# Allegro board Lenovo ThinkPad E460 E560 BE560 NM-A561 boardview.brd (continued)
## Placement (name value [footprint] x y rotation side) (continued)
NOREF#7  -  []  50.77 97.12 180 bottom
NOREF#8  -  []  28.57 60.15 90 bottom
NOREF#9  -  []  24.99 68.71 90 bottom
PC1  1U_0603_25V7K  [C_0603]  62.59 8.8 90 top
PC2  680P_0402_50V7-K  [C_0402]  238.87 174.28 0 bottom
PC3  0.1U_0402_6.3V  [C_0402]  238.89 175.17 0 bottom
PC4  1000P_0402_50V7-K  [C_0402]  233.51 158.66 270 bottom
PC5  100P_0402_50V8-J  [C_0402]  234.47 158.66 270 bottom
PC6  100P_0402_50V8J  [C_0402]  229.47 157.95 270 bottom
PC7  1000P_0402_50V7-K  [C_0402]  228.56 157.95 270 bottom
PC8  0.1U_0603_16V7K  [C_0603]  215.37 131.84 270 bottom
PC9  1000P_0402_50V  [C_0402]  192.49 181.14 180 bottom
PC10  0.01U_0402_25V  [C_0402]  202.11 183.63 270 bottom
PC101  470P_0402_50V  [C_0402]  223.25 162.68 180 bottom
PC102  0.022U_0402_25V  [C_0402]  223.7 159.81 270 bottom
PC103  10U_0805_25V6-K  [C_0805]  221.88 157.42 180 bottom
PC104  10U_0805_25V6-K  [C_0805]  224.85 175.81 180 bottom
PC105  0.1U_0402_25V7K  [C_0402]  180.45 165.04 270 bottom
PC106  0.1U_0402_25V7K  [C_0402]  181.31 165.04 0 bottom
PC107  1U_0603_25V7-K  [C_0603]  179.41 164.99 270 bottom
PC108  0.01U_0603_50V7K  [C_0603]  213.29 180 90 bottom
PC109  100P_0402_50V8-J  [C_0402]  180.98 165.9 0 bottom
PC110  2200P_0402_25V7-K  [C_0402]  193.66 172.15 270 bottom
PC111  47P_0402_50V8-J  [C_0402]  193.45 168.52 270 bottom
PC112  68P_0402_50V8-J  [C_0402]  192.49 168.52 270 bottom
PC113  10U_0805_25V6K  [C_0805]  192.31 170.93 90 bottom
PC114  10U_0805_25V6K  [C_0805]  190.58 170.93 90 bottom
PC115  1U_0603_25V  [C_0603]  182.3 169.1 270 bottom
PC116  4.7U_0603_10V6-M  [C_0603]  181.82 172.86 0 bottom
PC117  0.1U_0402_25V7K  [C_0402]  174.1 166.97 0 bottom
PC118  0.047U_0603_25V  [C_0603]  182.17 170.32 0 bottom
PC119  10U_0805_25V6-K  [C_0805]  204.02 184.02 270 bottom
PC120  10U_0805_25V6-K  [C_0805]  206.56 184.02 270 bottom
PC121  680P_0402_50V7K  [C_0402]  195.64 172.3 180 bottom
PC122  0.1U_0402_25V7K  [C_0402]  181.29 176.33 270 bottom
PC123  0.1U_0402_25V7K  [C_0402]  181.29 177.19 90 bottom
PC124  0.1U_0402_25V7K  [C_0402]  182.17 176.3 90 bottom
PC125  100P_0402_50V8J  [C_0402]  170.31 168.87 0 bottom
PC126  100P_0402_50V8J  [C_0402]  170.31 169.74 0 bottom
PC127  100P_0402_50V8J  [C_0402]  170.29 170.63 0 bottom
PC128  0.1U_0402_25V6  [C_0402]  175.24 177 180 bottom
PC201  0.1U_0402_25V6-K  [C_0402]  170.49 9.54 90 bottom
PC202  10U_0805_25V6-K  [C_0805]  172.7 9.01 90 bottom
PC203  0.1U_0603_25V7-M  [C_0603]  163.56 7.74 180 top
PC204  22U_0805_6.3V6-M  [C_0805]  153.93 9.03 90 bottom
PC205  22U_0805_6.3V6-M  [C_0805]  153.96 6.29 270 bottom
PC206  22U_0805_6.3V6-M  [C_0805]  152.13 6.29 270 bottom
PC207  22U_0805_6.3V6-M  [C_0805]  152.1 9.03 90 bottom
PC208  4.7U_0603_6.3V6-K  [C_0603]  169.54 4.64 0 bottom
PC209  680P_0402_50V7K  [C_0402]  165.56 9.97 180 top
PC210  2200P_0402_25V7-K  [C_0402]  150.7 9.49 90 bottom
PC211  0.1U_0402_25V6  [C_0402]  150.76 5.68 270 bottom
PC212  0.01U_0402_25V7-K  [C_0402]  166.86 4.18 270 bottom
PC213  0.1U_0402_25V6-K  [C_0402]  165.97 3.29 90 top
PC214  10U_0805_25V6-K  [C_0805]  179.61 6.28 270 bottom
PC215  0.1U_0402_25V6-K  [C_0402]  183.95 4.48 270 bottom
PC216  10U_0805_25V6-K  [C_0805]  181.34 6.28 270 bottom
PC217  0.1U_0603_25V7-M  [C_0603]  193.35 7.53 270 top
PC218  1U_0603_25V6M  [C_0603]  184.84 10.8 270 bottom
PC219  22U_0805_6.3V6-M  [C_0805]  200.46 6.29 270 bottom
PC220  22U_0805_6.3V6-M  [C_0805]  204.04 6.3 270 bottom
PC221  22U_0805_6.3V6-M  [C_0805]  202.24 6.29 270 bottom
PC222  22U_0805_6.3V6-M  [C_0805]  203.89 8.98 90 bottom
PC223  22U_0805_6.3V6-M  [C_0805]  200.31 8.98 90 bottom
PC224  22U_0805_6.3V6-M  [C_0805]  202.09 8.98 90 bottom
PC225  4.7U_0603_6.3V6-K  [C_0603]  183.55 9.4 90 bottom
PC226  680P_0402_50V7K  [C_0402]  190.94 3.09 0 top
PC227  2200P_0402_25V7-K  [C_0402]  205.49 5.7 270 bottom
PC228  0.1U_0402_25V6  [C_0402]  205.39 9.49 90 bottom
PC229  6800P_0402_25V7-K  [C_0402]  186.8 9.11 90 bottom
PC230  47P_0402_50V8-J  [C_0402]  171.38 9.54 90 bottom
PC231  47P_0402_50V8-J  [C_0402]  183.01 4.48 270 bottom
PC301  10U_0603_6.3V6M  [C_0603]  134.14 33.14 180 bottom
PC302  10U_0805_25V6-K  [C_0805]  140.54 27.6 270 bottom
PC303  10U_0805_25V6-K  [C_0805]  142.3 27.62 270 bottom
PC304  0.1U_0402_25V6  [C_0402]  136.1 29.81 90 bottom
PC305  47P_0402_50V8-J  [C_0402]  137.01 29.81 90 top
PC306  68P_0402_50V8J  [C_0402]  136.1 29.81 90 top
PC307  2200P_0402_25V  [C_0402]  137.01 29.81 90 bottom
PC308  10U_0603_6.3V6M  [C_0603]  132.49 35.63 270 bottom
PC309  0.1U_0402_6.3V7-K  [C_0402]  131.43 35.19 270 bottom
PC310  0.22U_0603_25V7K  [C_0603]  136.89 33.59 270 bottom
PC311  330U_D2_2V_R9M  [C_D2]  137.57 13.98 0 bottom
PC312  2200P_0402_25V7-K  [C_0402]  139.91 11.09 0 bottom
PC313  0.1U_0402_25V6  [C_0402]  132.34 12.26 180 bottom
PC314  470P_0402_50V7K  [C_0402]  131.55 41.06 0 bottom
PC315  0.033U_0402_16V7K  [C_0402]  132.34 39.38 180 bottom
PC316  1U_0402_10VA-K  [C_0402]  139.35 38.42 90 bottom
PC317  680P_0402_50V7K  [C_0402]  140.77 24.17 180 top
PC318  0.1U_0402_6.3V7-K  [C_0402]  134.25 41.82 180 bottom
PC319  0.1U_0402_16V  [C_0402]  135.08 41.82 0 bottom
PC401  0.01U_0402_25V7-K  [C_0402]  76.23 125.62 0 bottom
PC402  1U_0402_6.3V6-K  [C_0402]  76.23 124.75 0 bottom
PC403  0.1U_0402_6.3V6-K  [C_0402]  69.42 118.05 90 top
PC404  1000P_0402_25V7-K  [C_0402]  78.16 116.96 90 bottom
PC405  0.033U_0402_25V7K  [C_0402]  71.94 116.17 0 bottom
PC406  1000P_0402_25V7-K  [C_0402]  77.27 116.09 0 bottom
PC407  3300P_0402_50V7-K  [C_0402]  76.46 117.95 180 bottom
PC408  0.1U_0402_25V6-K  [C_0402]  76.59 120.56 90 bottom
PC409  15P_0402_50V8-J  [C_0402]  75.47 116.17 180 bottom
PC410  1500P_0402_50V7-K  [C_0402]  75.47 115.31 180 bottom
PC411  270P_0402_50V7-M  [C_0402]  71.15 118.99 270 top
PC412  1000P_0402_50V7-K  [C_0402]  73.11 118.96 270 top
PC413  1000P_0402_25V7-K  [C_0402]  63.89 125.03 0 bottom
PC414  0.1U_0402_25V6-K  [C_0402]  72.75 126.46 180 bottom
PC415  3300P_0402_50V7-K  [C_0402]  63.91 126.76 0 bottom
PC416  470P_0402_50V8-J  [C_0402]  68.84 123.64 90 top
PC417  0.1U_0402_16V7-K  [C_0402]  71.91 127.29 90 bottom
PC418  100P_0402_50V7-K  [C_0402]  70.08 126.46 0 bottom
PC419  1000P_0402_25V7-K  [C_0402]  70.08 127.34 0 bottom
PC420  2200P_0402_25V7-K  [C_0402]  68.36 128.23 270 bottom
PC421  470P_0402_50V8-J  [C_0402]  65.74 128.23 0 bottom
PC422  15P_0402_50V8-J  [C_0402]  67.47 126.48 0 bottom
PC423  1000P_0402_25V7-K  [C_0402]  62.9 122.77 90 bottom
PC424  0.1U_0402_25V6-K  [C_0402]  74.5 127.29 90 bottom
PC425  1000P_0402_25V7-K  [C_0402]  62.9 121.05 90 bottom
PC426  3300P_0402_50V7-K  [C_0402]  63.73 121.07 0 bottom
PC427  15P_0402_50V8-J  [C_0402]  63.73 119.34 0 bottom
PC428  0.01U_0402_25V6-K  [C_0402]  63.73 120.21 0 bottom
PC429  0.018U_0402_50V7-J  [C_0402]  63.96 117.39 90 bottom
PC430  270P_0402_50V7-M  [C_0402]  68.23 118.94 180 top
PC431  1000P_0402_50V7-K  [C_0402]  68.23 121.53 180 top
PC432  10U_0805_25V6-K  [C_0805]  138.46 97.14 270 bottom
PC433  10U_0805_25V6-K  [C_0805]  143.64 97.12 270 bottom
PC434  10U_0805_25V6-K  [C_0805]  141.92 97.12 270 bottom
PC435  10U_0805_25V6-K  [C_0805]  140.19 97.12 270 bottom
PC436  0.1U_0402_25V6  [C_0402]  137.06 96.1 270 bottom
PC437  2200P_0402_25V7-K  [C_0402]  135.29 96.1 270 bottom
PC438  47P_0402_50V8-J  [C_0402]  136.18 96.1 270 bottom
PC439  3300P_0402_50V7-K  [C_0402]  64.85 117.39 90 bottom
PC440  1000P_0402_50V7-K  [C_0402]  71.94 115.31 0 bottom
PC441  1U_0402_6.3V6-K  [C_0402]  66.71 116.12 270 bottom
PC442  0.22U_0603_25V7-K  [C_0603]  130.74 100.78 270 bottom
PC443  330U_D2_2VM_R9M  [C_D2]  124.99 109.82 90 bottom
PC444  1U_0402_10V  [C_0402]  125.51 103.65 0 bottom
PC445  680P_0402_50V7K  [C_0402]  143.97 113.48 0 bottom
PC446  10U_0805_25V6-K  [C_0805]  39.07 58.03 0 top
PC447  10U_0805_25V6-K  [C_0805]  39.07 58.03 0 bottom
PC448  10U_0805_25V6-K  [C_0805]  34.5 59.83 180 bottom
PC449  10U_0805_25V6-K  [C_0805]  34.5 59.83 180 top
PC450  0.1U_0402_25V6  [C_0402]  34.02 63.18 180 bottom
PC451  2200P_0402_25V7-K  [C_0402]  33.99 62.22 180 bottom
PC452  47P_0402_50V8-J  [C_0402]  33.99 61.28 180 bottom
PC453  0.22U_0603_25V7-K  [C_0603]  36.86 72.43 180 bottom
PC454  330U_D2_2VM_R9M  [C_D2]  45.29 80.38 180 bottom
PC455  1U_0402_10V  [C_0402]  39.83 76.47 270 bottom
PC456  680P_0402_50V7K  [C_0402]  48.6 59.53 90 top
PC457  10U_0805_25V6-K  [C_0805]  144.66 73.42 270 bottom
PC458  10U_0805_25V6-K  [C_0805]  142.93 73.45 270 bottom
PC459  0.1U_0402_25V6  [C_0402]  143.11 75.55 90 bottom
PC460  2200P_0402_25V7-K  [C_0402]  144 75.55 90 bottom
PC461  47P_0402_50V8-J  [C_0402]  144.89 75.55 90 bottom
PC462  0.22U_0603_25V7-K  [C_0603]  140.32 81.83 180 bottom
PC463  1U_0402_10V  [C_0402]  143.16 85.61 270 bottom
PC464  680P_0402_50V7K  [C_0402]  141.51 78.58 0 top
PC465  22U_0603_6.3V6M  [C_0603]  86.99 98.41 180 top
PC466  22U_0603_6.3V6M  [C_0603]  82.77 98.52 0 top
PC467  22U_0603_6.3V6M  [C_0603]  89.78 97.58 180 top
PC468  22U_0603_6.3V6M  [C_0603]  82.77 92.55 0 top
PC469  22U_0603_6.3V6M  [C_0603]  92.78 98.85 180 top
PC470  22U_0603_6.3V6M  [C_0603]  82.77 93.74 0 top
PC471  22U_0603_6.3V6M  [C_0603]  82.77 94.93 0 top
PC472  22U_0603_6.3V6M  [C_0603]  89.78 96.31 180 top
PC473  22U_0603_6.3V6M  [C_0603]  86.99 96.03 180 top
PC474  22U_0603_6.3V6M  [C_0603]  86.99 92.45 180 top
PC475  22U_0603_6.3V6M  [C_0603]  89.78 95.04 180 top
PC476  22U_0603_6.3V6M  [C_0603]  89.78 93.77 180 top
PC477  22U_0603_6.3V6M  [C_0603]  80.4 93.23 0 top
PC478  22U_0603_6.3V6M  [C_0603]  92.78 94.07 180 top
PC479  22U_0603_6.3V6M  [C_0603]  80.4 91.99 0 top
PC480  22U_0603_6.3V6M  [C_0603]  86.99 93.64 180 top
PC481  22U_0603_6.3V6M  [C_0603]  92.78 97.65 180 top
PC482  22U_0603_6.3V6M  [C_0603]  92.78 95.26 180 top
PC483  22U_0603_6.3V6M  [C_0603]  86.99 94.83 180 top
PC484  22U_0603_6.3V6M  [C_0603]  82.77 96.13 0 top
PC485  22U_0603_6.3V6M  [C_0603]  92.78 96.46 180 top
PC486  22U_0603_6.3V6M  [C_0603]  82.77 97.32 0 top
PC487  22U_0603_6.3V6M  [C_0603]  86.99 97.22 180 top
PC488  22U_0603_6.3V6M  [C_0603]  74.75 98.34 0 top
PC489  22U_0603_6.3V6M  [C_0603]  78.97 97.07 180 top
PC490  22U_0603_6.3V6M  [C_0603]  63.68 95.12 90 bottom
PC491  22U_0603_6.3V6M  [C_0603]  63.68 93.96 270 bottom
PC492  22U_0603_6.3V6M  [C_0603]  72.35 91.75 90 top
PC493  22U_0603_6.3V6M  [C_0603]  74.75 89.4 0 top
PC494  22U_0603_6.3V6M  [C_0603]  78.97 94.53 180 top
PC495  22U_0603_6.3V6M  [C_0603]  78.97 93.23 180 top
PC496  22U_0603_6.3V6M  [C_0603]  74.75 97.05 0 top
PC497  22U_0603_6.3V6M  [C_0603]  74.75 95.78 0 top
PC498  22U_0603_6.3V6M  [C_0603]  74.75 94.52 0 top
PC499  22U_0603_6.3V6M  [C_0603]  74.75 93.29 0 top
PC500  22U_0603_6.3V6M  [C_0603]  62.41 99.8 270 bottom
PC501  22U_0603_6.3V6M  [C_0603]  63.68 99.8 270 top
PC502  22U_0603_6.3V6M  [C_0603]  63.68 99.8 270 bottom
PC503  22U_0603_6.3V6M  [C_0603]  63.68 95.12 90 top
PC504  22U_0603_6.3V6M  [C_0603]  62.41 99.8 270 top
PC505  22U_0603_6.3V6M  [C_0603]  63.68 93.96 270 top
PC506  22U_0603_6.3V6M  [C_0603]  62.41 93.68 270 top
PC507  22U_0603_6.3V6M  [C_0603]  62.41 95.12 90 top
PC508  22U_0603_6.3V6M  [C_0603]  61.14 95.1 90 bottom
PC509  22U_0603_6.3V6M  [C_0603]  62.41 95.12 90 bottom
PC510  22U_0603_6.3V6M  [C_0603]  62.41 93.68 270 bottom
PC511  22U_0603_6.3V6M  [C_0603]  61.14 93.7 270 bottom
PC512  22U_0603_6.3V6M  [C_0603]  61.14 99.8 270 bottom
PC513  22U_0603_6.3V6M  [C_0603]  134.3 88.81 270 bottom
PC514  22U_0603_6.3V6M  [C_0603]  135.57 88.81 270 bottom
PC515  22U_0603_6.3V6M  [C_0603]  136.84 88.81 270 bottom
PC516  22U_0603_6.3V6M  [C_0603]  133.03 88.81 270 bottom
PC517  22U_0603_6.3V6M  [C_0603]  135.57 88.81 270 top
PC518  22U_0603_6.3V6M  [C_0603]  131.76 88.81 270 top
PC519  22U_0603_6.3V6M  [C_0603]  130.54 88.81 270 bottom
PC520  22U_0603_6.3V6M  [C_0603]  131.76 88.81 270 bottom
PC521  22U_0603_6.3V6M  [C_0603]  134.3 88.81 270 top
PC522  22U_0603_6.3V6M  [C_0603]  133.03 88.81 270 top
PC523  22U_0603_6.3V6M  [C_0603]  136.84 88.81 270 top
PC524  22U_0603_6.3V6M  [C_0603]  130.49 88.81 270 top
PC525  68U_25V_M_R0.36  [C_EEEFK1E680P]  32.54 52.39 180 bottom
PC526  68U_25V_M_R0.36  [C_EEEFK1E680P]  32.54 45.28 180 bottom
PC527  68U_25V_M_R0.36  [C_EEEFK1E680P]  38.87 51.47 270 bottom
PC528  33U_D2_25VM_R40M  [C_D2]  38.6 48.71 270 top
PC529  33U_D2_25VM_R40M  [C_D2]  43.55 48.71 270 top
PC601  0.1U_0402_25V6  [C_0402]  218.19 151.2 0 bottom
PC602  47P_0402_50V8-J  [C_0402]  196.4 142.43 180 top
PC603  2200P_0402_50V7K  [C_0402]  196.4 142.43 180 bottom
PC604  1U_0402_10V  [C_0402]  207.09 152.41 180 bottom
PC605  1U_0402_10V  [C_0402]  207.09 153.28 180 bottom
PC606  0.1U_0402_25V6  [C_0402]  196.4 141.54 180 bottom
PC607  10U_0805_25V6K  [C_0805]  196.22 143.88 180 top
PC608  0.22U_0603_25V  [C_0603]  213.99 145.77 0 top
PC609  100P_0402_50V8-J  [C_0402]  210.75 147.44 180 bottom
PC610  150P_0402_50V8-J  [C_0402]  208.06 146.57 0 bottom
PC611  10U_0805_25V6K  [C_0805]  196.22 143.88 180 bottom
PC612  0.22U_0603_25V  [C_0603]  206.69 149.11 90 bottom
PC613  330U_D2_2VM_R9M  [C_D2]  175.32 150.94 0 bottom
PC614  330U_D2_2VM_R9M  [C_D2]  175.32 146.24 0 bottom
PC615  0.1U_0402_25V6  [C_0402]  178.57 143.12 0 bottom
PC616  680P_0402_50V  [C_0402]  186.11 141.26 90 top
PC617  470P_0402_50V  [C_0402]  210.72 144.85 180 bottom
PC618  0.22U_0603_25V7-K  [C_0603]  206.81 156.78 270 bottom
PC619  330P_0402_50V7-K  [C_0402]  209 143.09 90 bottom
PC620  680P_0402_50V7-K  [C_0402]  208.08 144.01 270 bottom
PC621  330P_0402_50V7-K  [C_0402]  212.48 147.44 180 bottom
PC622  1000P_0402_25V7-K  [C_0402]  211.56 146.57 0 bottom
PC623  47P_0402_50V8-J  [C_0402]  196.37 154.09 180 top
PC624  2200P_0402_50V7K  [C_0402]  196.37 155.01 180 bottom
PC625  0.1U_0402_25V6  [C_0402]  196.37 154.09 180 bottom
PC626  10U_0805_25V6K  [C_0805]  196.25 152.77 180 bottom
PC627  10U_0805_25V6K  [C_0805]  196.25 152.77 180 top
PC628  0.22U_0603_25V  [C_0603]  213.99 146.98 0 top
PC629  330U_D2_2VM_R9M  [C_D2]  170.16 153.53 90 bottom
PC630  330U_D2_2VM_R9M  [C_D2]  170.52 142.74 180 bottom
PC631  0.1U_0402_25V6  [C_0402]  178.57 142.23 0 bottom
PC632  680P_0402_50V7K  [C_0402]  190.99 155.08 270 top
PC633  0.1U_0402_25V7K  [C_0402]  215.96 146.55 180 bottom
PC634  82N_0402_50V  [C_0402]  215.96 147.44 180 bottom
PC635  330P_0402_50V  [C_0402]  213.34 147.44 270 bottom
PC636  0.1U_0402_25V  [C_0402]  214.97 151.53 0 top
PC637  0.1U_0402_25V6  [C_0402]  214.31 143.91 90 bottom
PC701  0.1U_0402_16V7-K  [C_0402]  140.04 45.53 270 bottom
PC702  0.1U_0402_6.3V7-K  [C_0402]  141.81 44.64 180 bottom
PC703  0.01U_0402_25V7-K  [C_0402]  144.18 48.35 0 bottom
PC704  0.1U_0603_25V7K  [C_0603]  134.42 48.11 90 bottom
PC705  2.2U_0603_10V6-K  [C_0603]  144.89 51.53 270 bottom
PC706  68P_0402_50V8J  [C_0402]  142.45 53.41 180 top
PC707  10U_0805_25V6-K  [C_0805]  142.8 57.42 180 bottom
PC708  10U_0805_25V6-K  [C_0805]  142.8 55.67 180 bottom
PC709  2200P_0402_25V7-K  [C_0402]  142.45 54.29 180 bottom
PC710  0.1U_0402_25V6  [C_0402]  142.45 53.41 180 bottom
PC711  22U_0805_6.3V6-M  [C_0805]  133.28 63.64 180 bottom
PC712  22U_0805_6.3V6-M  [C_0805]  136.89 60.87 0 bottom
PC713  22U_0805_6.3V6-M  [C_0805]  136.89 62.57 0 bottom
PC714  47P_0402_50V8-J  [C_0402]  142.45 54.29 180 top
PC715  22U_0805_6.3V6-M  [C_0805]  133.28 61.46 180 bottom
PC716  2200P_0402_25V7-K  [C_0402]  132.37 67.6 180 bottom
PC717  0.1U_0402_25V6  [C_0402]  132.34 66.13 180 bottom
PC718  680P_0402_50V7K  [C_0402]  137.14 54.45 0 top
PC801  10U_0603_10V  [C_0603]  186.59 180.68 180 bottom
PC802  10U_0603_10V  [C_0603]  186.59 179.47 180 bottom
PC803  0.22U_0402_10V6-K  [C_0402]  184.16 185.4 180 bottom
PC804  680P_0402_50V  [C_0402]  182.81 183.68 90 top
PC805  22P_0402_50V  [C_0402]  190.18 184.01 270 bottom
PC806  22U_0805_6.3VAM  [C_0805]  171.91 181.6 180 bottom
PC807  22U_0805_6.3VAM  [C_0805]  171.91 179.87 180 bottom
PC808  0.1U_0402_25V6  [C_0402]  174.05 178.78 0 bottom
PD1  RB751V-40  [RB751V-40_SOD323-2]  71.23 14.16 0 top
PD2  1SS355  [RB751V-40_SOD323-2]  68.99 11.29 270 top
PD3  RB751V-40  [RB751V-40_SOD323-2]  71.23 12.51 0 top
PD4  -  [RB751V-40_SOD323-2]  244.46 162.09 180 top
PD5  -  [AZ5425-01F_DFN1006P2E2]  243.52 161.51 270 bottom
PD6  RB751V-40  [RB751V-40_SOD323-2]  230.87 153.46 180 top
PD7  -  [PESD5V0U2BT_SOT23-3]  200.21 182.03 0 top
PD101  RB751V-40  [RB751V-40_SOD323-2]  174.76 163.95 0 bottom
PD102  RB751V-40  [RB751V-40_SOD323-2]  187.25 166.73 180 bottom
PD103  RB751V-40  [RB751V-40_SOD323-2]  186.21 170.52 0 bottom
PD801  RB751V-40  [RB751V-40_SOD323-2]  181.54 186.2 0 top
PF1  7A_32V_0437007.WR  [F_0437007PWR]  236.3 159.4 90 bottom
PF2  12A_32V_0501012.WRS  [F_0437007PWR]  193.45 182.51 90 bottom
PJ201  -  [JUMP_43X79]  174.83 8.32 0 bottom
PJ202  -  [JUMP_43X118]  148.27 7.33 0 bottom
PJ203  -  [JUMP_43X79]  180.14 7.56 90 bottom
PJ204  -  [JUMP_43X118]  207.88 7.66 180 bottom
PJ301  -  [JUMP_43X118]  132.98 9.97 90 bottom
PJ302  -  [JUMP_43X118]  136.89 9.97 90 bottom
PJ303  -  [JUMP_43X39]  131.96 37.71 270 bottom
PJ304  -  [JUMP_43X79]  143.82 28.08 0 bottom
PJ701  -  [JUMP_43X79]  144.02 58.92 90 bottom
PJ702  -  [JUMP_43X118]  132.98 71.19 270 bottom
PJ703  -  [JUMP_43X118]  136.91 71.19 270 bottom
PJ801  -  [JUMP_43X39]  188.86 179.52 0 bottom
PJ802  -  [JUMP_43X39]  171.71 176.47 90 bottom
PL1  MURATA BLM18KG300TN1D  [TDK_MPZ1608S300AT_2P]  232.21 160.11 180 bottom
PL2  MURATA BLM18KG300TN1D  [TDK_MPZ1608S300AT_2P]  232.21 158.89 180 bottom
PL3  MURATA BLM18KG300TN1D  [TDK_MPZ1608S300AT_2P]  197.11 180.38 0 bottom
PL4  MURATA BLM18KG300TN1D  [TDK_MPZ1608S300AT_2P]  197.11 179.11 0 bottom
PL101  1UH_PCMB053T-1R0MS_20%  [CYNTE_PCMB053T-1R0MS_2P]  220.05 165.27 90 bottom
PL102  4.7UH_PCMB104T-4R7MS  [CYNTE_PCMB104T-100MS_2P]  201.56 171.97 0 bottom
PL201  2.2UH_PCMB063T-2R2MS_8A_20%  [CYNTE_PCMB063T-2R2MS_2P]  162.95 7.74 180 bottom
PL202  2.2UH_PCMB063T-2R2MS_8A_20%  [CYNTE_PCMB063T-2R2MS_2P]  191.4 7.71 0 bottom
PL301  1UH_PCMC063T-1R0MN_+-20%  [CYNTE_PCMB063T-1R0MS_2P]  134.58 18.28 90 bottom
PL401  BLM18KG300TN1D  [TDK_MPZ1608S300AT_2P]  143.54 100.37 0 bottom
PL402  BLM18KG300TN1D  [TDK_MPZ1608S300AT_2P]  143.54 99.15 0 bottom
PL403  CMLE064T-R15MS0R725-88(0.72mohm+/-5%)  [CYNTE_CMLE064T-R15MS0R66788_2P]  135.9 107.89 180 bottom
PL404  BLM18KG300TN1D  [TDK_MPZ1608S300AT_2P]  37.45 56.5 270 bottom
PL405  BLM18KG300TN1D  [TDK_MPZ1608S300AT_2P]  35.95 56.5 270 bottom
PL406  CMLE064T-R15MS0R725-88(0.72mohm+/-5%)  [CYNTE_CMLE064T-R15MS0R66788_2P]  46.13 69.15 90 bottom
PL407  BLM18KG300TN1D  [TDK_MPZ1608S300AT_2P]  145.98 74.08 0 top
PL408  0.47UH_PCMB063T-R47MS3R675_18A_20%(DCR+/-5%)  [CYNTE_CMLE064T-R15MS0R66788_2P]  134.6 77.84 90 bottom
PL601  MURATA BLM18KG300TN1D  [TDK_MPZ1608S300AT_2P]  200.49 143.4 0 bottom
PL602  MURATA BLM18KG300TN1D  [TDK_MPZ1608S300AT_2P]  200.51 144.74 0 bottom
PL603  .24UH 20% PCME063T-R24MS1R145 35A  [CYNTE_PCMB063T-1R0MS_2P]  182.02 138.17 180 bottom
PL604  .24UH 20% PCME063T-R24MS1R145 35A  [CYNTE_PCMB063T-1R0MS_2P]  181.49 157.11 180 bottom
PL701  1UH_PCMC063T-1R0MN_+-20%  [CYNTE_PCMB063T-1R0MS_2P]  134.52 52.08 90 bottom
PL801  1UH_PH041H-1R0MS_20%  [CYNTE_PH041H-1R0MS_2P]  180.5 182.31 180 bottom
PQ1  -  [MMBT3906_SOT23-3]  64.67 13.63 270 top
PQ2  -  [MMBT3904_SOT23-3]  66.66 9.59 90 top
PQ4  2N7002KDWH 2N SOT363-6  [2N7002BKS_SOT363-6]  240.7 158.97 270 bottom
PQ101  AON7466  [SIS406DN-T1-GE3_PAK1212-8-5]  225.35 159.7 90 bottom
PQ102  AON7466  [SIS406DN-T1-GE3_PAK1212-8-5]  221.9 161.28 270 bottom
PQ103  2N7002WT1G  [2N7002KW_SOT323-3]  223.4 159.15 270 top
PQ104  AON7466  [SIS406DN-T1-GE3_PAK1212-8-5]  214.81 178.75 90 bottom
PQ105  2N7002WT1G  [2N7002KW_SOT323-3]  173.16 163.97 270 bottom
PQ106  AON7408L  [SI7326DN-T1-E3_PAK1212-8]  197.82 170.83 270 bottom
PQ107  AON7408L  [SI7326DN-T1-E3_PAK1212-8]  194.95 173.8 90 bottom
PQ201  2N7002KDWH 2N  [2N7002BKS_SOT363-6]  173.74 5.53 270 bottom
PQ301  AON7408L  [SI7326DN-T1-E3_PAK1212-8]  134.85 26.74 180 bottom
PQ302  AON7534  [SI7326DN-T1-E3_PAK1212-8]  141.89 24.04 270 bottom
PQ401  TPCA8065-H  [TPCA8065-H_PPAK56-8-5]  132.92 102.81 0 bottom
PQ402  TPCA8057-H  [TPCA8059-H_PPAK56-8-5]  144.63 106.59 270 bottom
PQ403  TPCA8057-H  [TPCA8059-H_PPAK56-8-5]  144.63 112.05 270 bottom
PQ404  TPCA8065-H  [TPCA8065-H_PPAK56-8-5]  39.76 68.54 270 bottom
PQ405  TPCA8057-H  [TPCA8059-H_PPAK56-8-5]  51.21 59.81 180 bottom
PQ406  TPCA8057-H  [TPCA8059-H_PPAK56-8-5]  45.55 59.81 180 bottom
PQ407  AON7408L  [SI7326DN-T1-E3_PAK1212-8]  139.25 75.96 0 bottom
PQ408  AON7408L  [SI7326DN-T1-E3_PAK1212-8]  142.22 79.8 270 bottom
PQ601  TPCA8065-H  [TPCA8065-H_PPAK56-8-5]  194.8 136.01 90 bottom
PQ602  TPCA8057-H  [TPCA8059-H_PPAK56-8-5]  184.97 141.92 0 bottom
PQ603  TPCA8057-H  [TPCA8059-H_PPAK56-8-5]  192.59 141.92 180 top
PQ604  TPCA8065-H  [TPCA8065-H_PPAK56-8-5]  194.39 156.53 90 bottom
PQ605  TPCA8057-H  [TPCA8059-H_PPAK56-8-5]  192.41 153.46 180 bottom
PQ606  TPCA8057-H  [TPCA8059-H_PPAK56-8-5]  184.82 153.46 0 top
PR1  100K_0402_1%  [R_0402]  68.69 13.12 90 top
PR2  10K_0402_1%  [R_0402]  68.69 15.05 0 top
PR3  750K_0402_5%  [R_0402]  68.69 16.04 0 top
PR4  750_0402_1%  [R_0402]  238.77 161.46 90 bottom
PR5  1M_0402_5%  [R_0402]  243.67 158.54 180 bottom
PR6  0_0402_5%  [R_0402]  240.62 161.43 180 bottom
PR7  10K_0402_1%  [R_0402]  241.51 161.43 0 bottom
PR8  1M_0402_5%  [R_0402]  242.75 159.42 0 bottom
PR9  16.5K_0402_1%  [R_0402]  212.35 132.22 0 bottom
PR10  12.7K_0402_1%  [R_0402]  210.52 133.11 270 bottom
PR11  47K_0402_1%  [R_0402]  211.44 133.11 270 bottom
PR12  20K_0402_1%  [R_0402]  209.38 131.21 270 bottom
PR13  0_0402_5%  [R0402_SHORT]  215.22 128.49 90 bottom
PR14  100_0402_1%  [R_0402]  197.06 183.99 180 top
PR15  100_0402_1%  [R_0402]  197.06 184.85 180 top
PR16  100K_0402_1%  [R_0402]  203.46 185.08 0 top
PR17  10K_0402_1%  [R_0402]  204.37 184.16 180 top
PR18  3.01K_0402_1%  [R_0402]  227.7 154.68 270 top
PR19  43K_0402_1%  [R_0402]  228.59 155.63 270 top
PR101  0.01_1206_1%  [R_1206]  219.84 175.92 90 bottom
PR102  4.7_0603_5%  [R_0603]  224.24 161.91 180 top
PR103  499K_0402_1%  [R_0402]  212.17 180.91 270 bottom
PR104  1M_0402_5%  [R_0402]  226.32 158.51 90 top
PR105  1M_0402_5%  [R_0402]  226.02 157.16 180 top
PR106  10_0402_1%  [R_0402]  180.12 166.05 90 bottom
PR107  10_0402_1%  [R_0402]  179.23 166.05 90 bottom
PR108  1K_0402_1%  [R_0402]  180.98 166.77 0 bottom
PR109  0_0402_5%  [R0402_SHORT]  169.4 164.66 270 bottom
PR110  10K_0402_1%  [R_0402]  170.31 164.66 270 bottom
PR111  4.02K_0603_1%  [R_0603]  176.94 165.52 90 bottom
PR112  4.02K_0603_1%  [R_0603]  178.16 165.52 90 bottom
PR113  432K_0402_1%  [R_0402]  174.1 165.22 0 bottom
PR114  10_1206_5%  [R_1206]  183.62 168.62 0 bottom
PR115  68K_0402_1%  [R_0402]  174.1 166.11 0 bottom
PR116  2.2_0603_5%  [R_0603]  182.2 171.62 0 bottom
PR117  0.01_1206_1%  [R_1206]  209.8 178.98 180 bottom
PR118  0_0402_5%  [R0402_SHORT]  175.88 166.05 90 bottom
PR119  4.7_0603_5%  [R_0603]  196.55 172.3 0 bottom
PR120  0_0402_5%  [R0402_SHORT]  172.04 172.58 0 bottom
PR121  0_0402_5%  [R0402_SHORT]  172.04 173.47 0 bottom
PR122  0_0402_5%  [R0402_SHORT]  172.04 168.87 0 bottom
PR123  0_0402_5%  [R0402_SHORT]  172.04 169.74 0 bottom
PR124  0_0402_5%  [R0402_SHORT]  172.04 170.65 0 bottom
PR125  10_0603_5%  [R_0603]  180.33 176.13 180 bottom
PR126  0_0402_5%  [R0402_SHORT]  172.04 171.57 0 bottom
PR128  10_0603_5%  [R_0603]  180.33 177.33 180 bottom
PR129  0_0402_5%  [R0402_SHORT]  176.08 177.89 0 bottom
PR130  316K_0402_1%  [R_0402]  176.99 178.78 180 bottom
PR131  18.2K_0402_1%  [R_0402]  176.1 177.03 270 bottom
PR132  100K_0402_1%  [R_0402]  175.24 176.14 180 bottom
PR201  1M_0402_5%  [R_0402]  170.49 9.54 90 top
PR202  0_0603_5%  [R0603_SHORT]  165.92 7.74 180 top
PR203  0_0402_5%  [R0402_SHORT]  167.7 4.15 0 bottom
PR204  4.7_0603_5%  [R_0603]  163.63 9.97 180 top
PR205  0_0402_5%  [R0402_SHORT]  169.5 3.57 0 bottom
PR206  2.2K_0402_1%  [R_0402]  165.08 3.29 90 top
PR207  1K_0402_1%  [R_0402]  167.7 3.29 0 bottom
PR208  1M_0402_5%  [R_0402]  166.86 4.18 270 top
PR209  100K_0402_5%  [R_0402]  187.69 10.89 270 bottom
PR210  0_0402_5%  [R_0402]  188.55 10.89 270 bottom
PR211  0_0402_5%  [R_0402]  187.66 9.13 0 bottom
PR212  0_0603_5%  [R0603_SHORT]  191.98 6.06 90 top
PR213  0_0402_5%  [R0402_SHORT]  185.93 9.11 90 bottom
PR214  4.7_0603_5%  [R_0603]  191.78 4.23 0 top
PR215  1K_0402_1%  [R_0402]  186.82 10.86 180 bottom
PR216  47K_0402_1%  [R_0402]  174.71 2.99 90 bottom
PR217  47K_0402_1%  [R_0402]  173.82 2.99 90 bottom
PR301  100K_0402_1%  [R_0402]  140.24 40.3 180 bottom
PR302  220K_0402_1%  [R_0402]  140.24 37.56 180 bottom
PR303  2.2_0603_5%  [R_0603]  135.34 32.25 90 bottom
PR304  4.7_0603_5%  [R_0603]  138.61 24.42 90 top
PR305  7.87K_0402_1%  [R_0402]  131.55 41.92 0 bottom
PR306  5.1_0603_5%  [R_0603]  141.66 38.62 180 bottom
PR307  10K_0402_1%  [R_0402]  132.47 42.79 180 bottom
PR308  100K_0402_1%  [R_0402]  139.33 41.16 0 bottom
PR309  887K_0402_1%  [R_0402]  136.86 42.69 270 bottom
PR310  0_0402_5%  [R0402_SHORT]  133.33 42.66 90 bottom
PR311  0_0402_5%  [R_0402]  134.19 42.66 90 bottom
PR312  0_0402_5%  [R0402_SHORT]  136 43.55 180 bottom
PR313  47K_0402_5%  [R_0402]  136 42.69 180 bottom
PR401  1K_0402_5%  [R_0402]  77.15 126.48 180 bottom
PR402  2_0402_5%  [R_0402]  77.15 123.89 180 bottom
PR403  100_0402_5%  [R_0402]  70.16 116.73 270 top
PR404  47_0402_5%  [R_0402]  69.3 116.73 270 top
PR405  12K_0402_1%  [R_0402]  71.94 114.47 270 bottom
PR406  10K_0402_1%  [R_0402]  65.84 116.12 270 bottom
PR407  0_0402_5%  [R0402_SHORT]  67.6 115.23 90 bottom
PR408  0_0402_5%  [R0402_SHORT]  69.32 115.23 90 bottom
PR409  75_0402_5%  [R_0402]  71.05 116.14 270 bottom
PR410  51_0402_5%  [R_0402]  68.46 115.23 90 bottom
PR411  10_0402_5%  [R_0402]  70.19 115.23 90 bottom
PR412  7.5K_0603_1%  [R_0603]  70.8 113.7 270 bottom
PR413  16.5K_0402_1%  [R_0402]  68.23 122.8 180 top
PR414  3.24K_0402_1%  [R_0402]  78.19 118.71 180 bottom
PR415  3.24K_0402_1%  [R_0402]  77.3 116.96 90 bottom
PR416  910_0402_1%  [R_0402]  76.46 117.08 180 bottom
PR417  0_0402_5%  [R0402_SHORT]  76.56 119.72 0 bottom
PR418  61.9K_0402_1%  [R_0402]  77.45 121.48 270 bottom
PR419  2.49K_0402_1%  [R_0402]  76.31 116.19 270 bottom
PR420  48.7K_0402_1%  [R_0402]  72.24 118.96 270 top
PR421  107K_0402_1%  [R_0402]  70.29 118.07 90 top
PR422  2.05K_0402_1%  [R_0402]  73.64 126.43 90 bottom
PR423  10_0402_1%  [R_0402]  72.78 127.29 90 bottom
PR424  1.21K_0402_1%  [R_0402]  63.91 125.9 0 bottom
PR425  26.1K_0402_1%  [R_0402]  69.7 123.64 90 top
PR426  52.3K_0603_1%  [R_0603]  71 127.52 0 top
PR427  73.2K_0402_1%  [R_0402]  69.2 128.21 0 bottom
PR428  1K_0402_5%  [R_0402]  66.63 126.48 90 bottom
PR429  4.75K_0402_1%  [R_0402]  67.49 127.32 90 bottom
PR430  165K_0402_1%  [R_0402]  70.08 128.23 270 top
PR431  49.9_0402_1%  [R_0402]  65.77 126.48 90 bottom
PR432  12.4K_0402_1%  [R_0402]  69.22 126.46 90 bottom
PR433  2.7K_0402_1%  [R_0402]  63.73 123.66 0 bottom
PR434  2.7K_0402_1%  [R_0402]  63.73 122.8 0 bottom
PR435  0_0402_5%  [R0402_SHORT]  74.48 126.46 0 bottom
PR436  61.9K_0402_1%  [R_0402]  75.37 128.23 270 bottom
PR437  1K_0402_1%  [R_0402]  63.73 121.93 0 bottom
PR438  7.5K_0603_1%  [R_0603]  63.79 117.44 90 top
PR439  12K_0402_1%  [R_0402]  63.07 117.39 90 bottom
PR440  1.5K_0402_1%  [R_0402]  62.87 119.29 90 bottom
PR441  41.2K_0402_1%  [R_0402]  68.23 120.66 180 top
PR442  113K_0402_1%  [R_0402]  68.23 119.8 180 top
PR443  24K_0402_1%  [R_0402]  72.88 124.6 0 top
PR444  24K_0402_1%  [R_0402]  72.88 123.66 0 top
PR445  48.7K_0402_1%  [R_0402]  72.88 122.77 0 top
PR446  90.9K_0402_1%  [R_0402]  72.88 121.91 0 top
PR447  15.8K_0402_1%  [R_0402]  72.88 121.05 0 top
PR448  10K_0402_1%  [R_0402]  72.88 120.18 0 top
PR449  2.2_0603_1%  [R_0603]  129.32 99.35 180 bottom
PR450  4.7_0603_5%  [R_0603]  143.08 113.55 180 bottom
PR451  0_0402_5%  [R0402_SHORT]  71.94 111.22 90 bottom
PR452  0_0402_5%  [R0402_SHORT]  73.69 115.28 90 bottom
PR453  2.2_0603_1%  [R_0603]  35.41 73.7 90 bottom
PR454  4.7_0603_5%  [R_0603]  48.55 61.41 90 top
PR455  0_0402_5%  [R0402_SHORT]  73.64 129.66 270 bottom
PR456  0_0402_5%  [R0402_SHORT]  72.78 129.94 270 bottom
PR457  2.2_0603_1%  [R_0603]  138.97 83.25 90 bottom
PR458  4.7_0603_5%  [R_0603]  140.47 78.25 90 top
PR459  0_0402_5%  [R0402_SHORT]  62.72 117.39 90 top
PR460  0_0402_5%  [R0402_SHORT]  64.83 117.39 90 top
PR601  0_0603_5%  [R0603_SHORT]  204.81 152.19 180 bottom
PR602  0_0603_5%  [R0603_SHORT]  204.81 153.41 180 bottom
PR603  0_0402_5%  [R0402_SHORT]  221.37 151.2 180 bottom
PR604  10K_0402_1%  [R_0402]  208.97 146.57 180 top
PR605  0_0402_5%  [R0402_SHORT]  208.06 147.44 0 top
PR606  0_0402_5%  [R0402_SHORT]  219.11 150.05 180 bottom
PR607  4.7_0603_5%  [R_0603]  187.23 141.14 270 top
PR608  3.65K_0402_1%  [R_0402]  214.31 142.15 90 bottom
PR609  0_0402_5%  [R0402_SHORT]  219.11 155.54 180 bottom
PR610  0_0402_5%  [R0402_SHORT]  219.11 154.68 180 bottom
PR611  0_0402_5%  [R0402_SHORT]  219.11 152.08 180 bottom
PR612  0_0402_5%  [R0402_SHORT]  219.11 152.95 180 bottom
PR613  42.2K_0402_1%  [R_0402]  209 145.71 180 bottom
PR614  0_0603_5%  [R0603_SHORT]  209.15 149.19 180 bottom
PR615  0_0402_5%  [R0402_SHORT]  219.11 153.81 180 bottom
PR616  10K_0402_1%  [R_0402]  215.46 144.69 180 top
PR617  499_0402_1%  [R_0402]  209.84 145.68 90 bottom
PR618  1_0402_1%  [R_0402]  215.17 144.82 270 bottom
PR619  32.4K_0402_1%  [R_0402]  208.06 147.44 0 bottom
PR620  0_0603_5%  [R0603_SHORT]  209.33 156.66 180 bottom
PR621  0_0402_5%  [R0402_SHORT]  211.61 143.12 180 bottom
PR622  10_0402_1%  [R_0402]  209.86 143.09 90 bottom
PR623  1.1K_0402_1%  [R_0402]  210.7 145.68 90 bottom
PR624  2.7K_0402_1%  [R_0402]  209 144.85 180 bottom
PR625  0_0402_5%  [R0402_SHORT]  211.59 144.87 270 bottom
PR626  10_0402_1%  [R_0402]  211.56 145.71 0 bottom
PR627  10K_0402_5%  [R_0402]  213.59 154.7 90 top
PR628  10K_0402_1%  [R_0402]  211.87 155.61 270 top
PR629  10K_0402_1%  [R_0402]  212.73 155.61 270 top
PR630  4.7_0603_5%  [R_0603]  191.04 156.22 0 top
PR631  3.65K_0402_1%  [R_0402]  216.9 144.82 270 bottom
PR632  10K_0402_1%  [R_0402]  216.31 146.47 270 top
PR633  2.61K_0402_1%  [R_0402]  216.8 145.63 90 bottom
PR634  11K_0402_1%  [R_0402]  215.96 145.66 180 bottom
PR635  649_0402_1%  [R_0402]  214.2 147.44 270 bottom
PR636  1_0402_1%  [R_0402]  216.03 144.82 270 bottom
PR637  0_0402_5%  [R_0402]  214.46 154.7 90 top
PR638  100K_0402_1%  [R_0402]  215.32 155.61 270 top
PR639  100_0402_1%  [R_0402]  213.32 145.66 0 bottom
PR640  100K_0402_1%  [R_0402]  215.86 153.86 180 top
PR641  27.4K_0402_1%  [R_0402]  218.19 149.19 0 bottom
PR642  130K_0402  [R_0402]  215.88 152.39 180 top
PR643  10.7K_0402_1%  [R_0402]  220.53 150.28 0 bottom
PR701  0_0402_5%  [R0402_SHORT]  139.17 44.62 90 bottom
PR702  210K_0402_1%  [R_0402]  141.81 45.51 180 bottom
PR703  210K_0402_1%  [R_0402]  142.65 44.62 90 bottom
PR704  100K_0402_1%  [R_0402]  138.28 45.53 270 bottom
PR705  0_0402_5%  [R_0402]  137.34 46.55 270 bottom
PR706  0_0402_5%  [R_0402]  145.09 49.21 180 bottom
PR707  0_0603_5%  [R0603_SHORT]  136.2 49.38 270 bottom
PR708  4.7_0603_5%  [R_0603]  136.91 53.46 270 top
PR801  0_0402_5%  [R0402_SHORT]  182.2 187.47 0 top
PR802  1M_0402_5%  [R_0402]  183.24 186.29 0 bottom
PR803  4.7_0603_5%  [R_0603]  181.67 184.82 270 top
PR804  20K_0402_1%  [R_0402]  189.29 184.01 270 bottom
PR805  10K_0402_1%  [R_0402]  191.06 183.1 90 bottom
PRT1  540_0402NEW_30%  [R_0402]  32.98 66.38 90 bottom
PRT2  540_0402NEW_30%  [R_0402]  198.79 134.63 180 bottom
PRT3  540_0402NEW_30%  [R_0402]  131.55 29.45 270 bottom
PRT4  540_0402NEW_30%  [R_0402]  140.75 71.69 180 bottom
PRT5  540_0402NEW_30%  [R_0402]  133.43 96.03 180 bottom
PRT6  540_0402NEW_30%  [R_0402]  195.23 167.53 0 bottom
PRT7  100K_0402_1%_NCP15WF104F03RC  [R_0402]  97.31 96.69 90 top
PRT401  MURAT_NCP15WF104F03RC  [R_0402-TH]  132.01 112.31 0 bottom
PRT402  MURAT_NCP15WF104F03RC  [R_0402-TH]  128.38 103.67 180 bottom
PRT403  MURAT_NCP15WM224J03RC  [R_0402-TH]  41.79 74.97 270 bottom
PRT404  MURAT_NCP15WF104F03RC  [R_0402-TH]  35.44 69.99 180 bottom
PRT405  MURAT_NCP15WF104F03RC  [R_0402-TH]  130.36 82.97 90 bottom
PRT601  10K_0402_NTC  [R_0402]  177.55 134.02 180 bottom
PRT602  470K_0402NEW_3%  [R_0402]  201.76 137.83 270 bottom
PU1  -  [G718TM1U_SOT23-8]  213.77 130.93 270 bottom
PU101  BQ24780SRUYR  [BQ24780RUYR_QFN24_4X4]  178.49 169.71 180 bottom
PU201  -  [SYX198BQNC_QFN10_3X3]  166.63 6.57 90 bottom
PU202  -  [SYX198CQNC_QFN10_3X3]  187.84 7.61 270 bottom
PU301  RT8231AGQW  [RT8231AGQW_WQFN20_3X3]  134.14 37.23 0 bottom
PU401  -  [NCP81208MNTXG_QFN48_6X6]  68.36 124.17 270 bottom
PU402  -  [NCP81253MNTBG_DFN8_2X2]  126.35 101.13 90 bottom
PU403  NCP81151MNTBG_DFN8_2X2  [NCP81253MNTBG_DFN8_2X2]  37.22 75.71 0 bottom
PU404  -  [NCP81253MNTBG_DFN8_2X2]  140.65 85.54 0 bottom
PU601  -  [ISL62771HRTZ_TQFN40_5X5]  215.53 154.65 180 bottom
PU701  TPS51367RVER  [TPS51367RVER_QFN28_3P5X4P5]  139.12 48.1 90 bottom
PU801  RT8068AZQW  [RT8068AZQW_WDFN10_3X3]  183.22 182.18 90 bottom
Q1  S TR TTC4116FU NPN SC-70-3  [MMST3904-7-F_SOT323-3]  33.07 105.19 180 bottom
Q2  S TR TTC4116FU NPN SC-70-3  [MMST3904-7-F_SOT323-3]  50.78 38.64 180 bottom
Q5  2N7002WT1G_1N_SC-70-3  [2N7002KW_SOT323-3]  214.15 33.92 180 top
Q6  -  [2N7002KDWH_SOT363-6]  206.94 137.45 0 top
Q22  -  [AO3401A_SOT23-3]  13.39 101.03 0 bottom
Q23  -  [AO4430L_SO8]  66.94 59.22 270 top
Q24  -  [2N7002KDWH_SOT363-6]  132.96 45.85 180 bottom
Q26  -  [AO3413_SOT23-3]  217.53 36.29 180 top
Q27  -  [AO3413_SOT23-3]  120.91 126.48 270 bottom
QC1  -  [2N7002KDWH_SOT363-6]  77.26 131.65 270 bottom
QC2  -  [2N7002KDWH_SOT363-6]  115.55 95.98 90 bottom
QC3  -  [2N7002KDWH_SOT363-6]  75.96 132.45 270 top
QD1  -  [DTC115TMT2L_VMT3]  109.4 21.76 270 top
QE1  2N7002WT1G_1N_SC-70-3  [2N7002KW_SOT323-3]  185.98 38.1 0 top
QG1  -  [AO3413_SOT23-3]  199.8 67.5 90 top
QG2  -  [2N7002KDWH_SOT363-6]  211.5 67.06 0 top
QL2  -  [AO3413_SOT23-3]  51.72 125.01 270 top
QL3  2N7002WT1G_1N_SC-70-3  [2N7002KW_SOT323-3]  55.06 121.58 270 top
QT1  -  [2N7002KDWH_SOT363-6]  16.06 90.21 270 bottom
QV1  2N7002WT1G_1N_SC-70-3  [2N7002KW_SOT323-3]  155.4 114.47 90 top
QV4  S TR TTC4116FU NPN SC-70-3  [MMST3904-7-F_SOT323-3]  171.92 130.98 90 top
QV5  -  [2N7002KDWH_SOT363-6]  162.47 143.89 0 top
QV6  -  [AO3413_SOT23-3]  174.58 129.28 0 top
QV9  -  [AO4430L_SO8]  183.78 128.44 90 bottom
QV17  2N7002WT1G_1N_SC-70-3  [2N7002KW_SOT323-3]  190.3 130 180 top
QV18  -  [2N7002KDWH_SOT363-6]  186.6 128.78 0 top
QV19  -  [2N7002KDWH_SOT363-6]  178.68 125.61 270 top
QV23  -  [2N7002KDWH_SOT363-6]  165.55 180.49 90 top
QV24  TPCA8057-H  [TPCA8059-H_PPAK56-8-5]  167.03 186.15 270 top
R2  100K_0402_5%  [R_0402]  92.11 139.41 135 bottom
R3  10K_0402_5%  [R_0402]  114.76 185.13 180 bottom
R17  0_0402_5%  [R_0402]  92.58 141.37 45 bottom
R18  100K_0402_5%  [R_0402]  88.95 132.37 135 bottom
R21  100K_0402_5%  [R_0402]  100.2 132.94 135 top
R25  2.2K_0402_1%  [R_0402]  98.93 131.67 135 top
R26  100K_0402_5%  [R_0402]  98.13 131 135 top
R28  47K_0402_5%  [R_0402]  213.87 36.26 270 top
R51  10K_0402_5%  [R_0402]  214.79 35.35 90 top
R59  4.7K_0402_5%  [R_0402]  182.94 123.94 270 top
R60  4.7K_0402_5%  [R_0402]  182.07 123.94 270 top
R61  4.7K_0402_5%  [R_0402]  30.88 104.03 0 top
R63  4.7K_0402_5%  [R_0402]  30.88 97.14 0 top
R64  0_0402_5%  [R0402_SHORT]  30.96 102.25 90 top
R65  4.7K_0402_5%  [R_0402]  30.88 96.25 0 top
R66  0_0402_5%  [R_0402]  31.85 102.25 90 top
R67  100K_0402_5%  [R_0402]  30.88 99.45 0 top
R68  0_0603_5%  [R0603_SHORT]  60.03 120.84 90 bottom
R69  100K_0402_5%  [R_0402]  211.31 32.53 180 top
R70  0_0402_5%  [R0402_SHORT]  214.99 92.75 0 top
R71  100K_0402_5%  [R_0402]  219.92 122.29 0 bottom
R89  100_0402_1%  [R_0402]  240.09 166.16 180 bottom
R90  100_0402_1%  [R_0402]  240.09 167.04 180 bottom
R91  100K_0402_5%  [R_0402]  240.09 165.27 180 bottom
R105  0_0402_5%  [R_0402]  32.62 104.92 180 top
R106  100K_0402_5%  [R_0402]  232.16 146.97 225 bottom
R107  100K_0402_5%  [R_0402]  230.24 145.06 45 bottom
R108  100K_0402_5%  [R_0402]  22.66 54.65 0 top
R111  300_0402_5%  [R_0402]  172.4 120.61 270 top
R112  1K_0603_5%  [R_0603]  231.98 156.45 270 bottom
R150  0_0402_5%  [R_0402]  223.75 60.36 0 bottom
R151  0_0402_5%  [R_0402]  240.04 171.87 180 bottom
R152  0_0402_5%  [R_0402]  240.04 172.76 180 bottom
R153  100K_0402_5%  [R_0402]  220.45 45.12 0 bottom
R154  0_0805_5%  [R_0805]  224.34 49.35 270 bottom
R156  100K_0402_5%  [R_0402]  205.92 141.39 270 top
R157  100K_0402_5%  [R_0402]  206.94 141.39 270 top
R159  47_0603_5%  [R_0603]  209.51 138.77 270 top
R163  0_0402_5%  [R_0402]  239.75 175.06 90 top
R164  0_0402_5%  [R_0402]  238.79 175.06 90 top
R165  0_0402_5%  [R_0402]  89.96 123.05 45 top
R166  0_0402_5%  [R_0402]  89.29 123.71 45 top
R167  0_0402_5%  [R_0402]  88.52 124.24 45 top
R168  0_0402_5%  [R_0402]  87.88 124.89 45 top
R169  0_0402_5%  [R_0402]  232.34 143.17 90 top
R170  0_0402_5%  [R_0402]  231.45 143.17 90 top
R171  0_0402_5%  [R_0402]  238.52 155.43 225 bottom
R172  0_0402_5%  [R_0402]  239.23 154.71 225 bottom
R173  0_0402_5%  [R_0402]  233.74 159.68 0 top
R174  0_0402_5%  [R_0402]  233.74 158.66 0 top
R175  0_0402_5%  [R_0402]  228.53 143.68 90 top
R176  0_0402_5%  [R_0402]  229.55 143.68 90 top
R177  0_0402_5%  [R_0402]  239.4 179.62 0 top
R178  0_0402_5%  [R_0402]  239.4 180.63 0 top
R217  100K_0402_5%  [R_0402]  234.98 145.25 0 top
R224  2.2K_0402_5%  [R_0402]  15.55 67.4 90 bottom
R225  2.2K_0402_5%  [R_0402]  14.66 67.4 90 bottom
R229  0_0402_5%  [R0402_SHORT]  17.33 80.25 270 top
R230  0_0402_5%  [R0402_SHORT]  17.33 82.54 270 top
R231  0_0402_5%  [R0402_SHORT]  17.33 84.83 270 top
R233  100K_0402_5%  [R_0402]  227.59 130.34 180 bottom
R234  100K_0402_5%  [R_0402]  227.59 129.45 180 bottom
R235  0_0402_5%  [R_0402]  227.59 131.23 180 bottom
R236  0_0805_5%  [R_0805]  247.33 159.68 90 bottom
R237  0_0805_5%  [R_0805]  245.55 159.68 90 bottom
R238  1K_0402_5%  [R_0402]  221.16 15.86 270 top
R239  1K_0402_5%  [R_0402]  239.12 170.98 0 bottom
R484  20K_0402_1%  [R_0402]  34.68 15.38 270 top
R9449  100K_0402_5%  [R_0402]  112.83 72.05 270 top
R9460  0_0402_5%  [R0402_SHORT]  212.22 31.54 90 top
R9472  0_0402_5%  [R_0402]  236.48 141.77 0 top
R9473  0_0402_5%  [R_0402]  236.48 140.88 0 top
R9474  0_0805_5%  [R0805_SHORT]  102.81 134.68 135 top
R9475  0_0402_5%  [R0402_SHORT]  99.57 132.3 135 top
R9476  20K_0402_1%  [R_0402]  35.57 15.38 270 top
R9477  10K_0402_5%  [R_0402]  118.57 116.04 270 bottom
R9478  0_0402_5%  [R_0402]  120.38 68.11 0 top
R9479  33_0402_5%  [R_0402]  115.91 115.12 90 bottom
R9480  10K_0402_5%  [R_0402]  112.91 125.26 270 bottom
R9481  33_0402_5%  [R_0402]  113.24 115.12 90 bottom
R9482  33_0402_5%  [R_0402]  116.8 115.12 90 bottom
R9483  33_0402_5%  [R_0402]  117.68 115.12 90 bottom
R9484  10K_0402_5%  [R_0402]  110.98 118.78 0 bottom
R9485  10K_0402_5%  [R_0402]  71.33 53.96 270 top
R9486  100K_0402_5%  [R_0402]  135.06 46.62 180 bottom
R9487  0_0402_5%  [R_0402]  70.41 53.05 90 top
R9488  10K_0402_1%  [R_0402]  129.34 67.98 90 top
R9489  10K_0402_5%  [R_0402]  122.66 125.8 90 bottom
R9490  0_0805_5%  [R_0805]  65.88 112.05 0 top
R9491  100_0402_5%  [R_0402]  117.07 126.43 180 bottom
R9492  0_0402_5%  [R_0402]  126.24 66.52 180 top
R9493  10K_0402_5%  [R_0402]  126.24 67.41 180 top
RA1  0_0805_5%  [R0805_SHORT]  194.1 20.44 0 top
RA2  0_0805_5%  [R_0805]  207.19 14.76 270 top
RA3  0_0805_5%  [R_0805]  205.47 13.06 90 top
RA4  0_0805_5%  [R0805_SHORT]  200.42 14.52 180 top
RA5  33_0402_5%  [R_0402]  209.86 26.99 270 top
RA8  BLM18PG221SN1D_2P  [MURAT_BLM18PG221SN1D_2P]  201.49 22.39 180 top
RA9  BLM18PG221SN1D_2P  [MURAT_BLM18PG221SN1D_2P]  201.49 24.68 180 top
RA10  BLM18PG221SN1D_2P  [MURAT_BLM18PG221SN1D_2P]  201.49 21.12 180 top
RA11  33_0402_5%  [R_0402]  200.21 29.1 0 top
RA12  BLM18PG221SN1D_2P  [MURAT_BLM18PG221SN1D_2P]  201.49 18.84 180 top
RA13  10K_0402_5%  [R_0402]  202.85 28.21 270 top
RA14  100_0402_5%  [R_0402]  213.85 17.54 0 top
RA15  100_0402_5%  [R_0402]  213.85 18.43 0 top
RA16  3K_0402_5%  [R_0402]  216.64 12.16 90 top
RA17  75_0402_5%  [R_0402]  216.64 11.34 270 top
RA18  5.11K_0402_1%  [R_0402]  215.12 22.29 180 top
RA19  100_0402_5%  [R_0402]  213.85 19.32 0 top
RA20  20K_0402_1%  [R_0402]  215.12 24.07 180 top
RA21  39.2K_0402_1%  [R_0402]  215.12 23.18 180 top
RA22  3K_0402_5%  [R_0402]  218.6 12.16 90 top
RA23  75_0402_5%  [R_0402]  218.6 11.34 270 top
RA24  100_0402_5%  [R_0402]  213.85 20.21 0 top
RA25  0_0402_5%  [R_0402]  196.04 26.38 270 top
RA27  0_0402_5%  [R0402_SHORT]  196.93 26.38 270 top
RA28  0_0402_5%  [R0402_SHORT]  214.97 27.6 270 top
RA29  47K_0402_5%  [R_0402]  217.94 22.32 180 top
RA30  0_0805_5%  [R0805_SHORT]  204.01 14.47 180 top
RA31  33_0402_5%  [R_0402]  215.12 24.96 180 top
RA32  0_0805_5%  [R0805_SHORT]  214.81 14.23 270 top
RC1  2.2K_0402_5%  [R_0402]  116.39 99.86 180 top
RC2  2.2K_0402_5%  [R_0402]  118.24 98.82 180 top
RC3  51_0201_5%  [R_0201]  73.97 115.44 90 top
RC4  51_0201_5%  [R_0201]  73.84 110.81 90 top
RC5  499_0402_1%  [R_0402]  71.67 113.64 0 top
RC6  51_0201_5%  [R_0201]  75.85 114.02 180 bottom
RC8  121_0402_1%  [R_0402]  98.61 82.22 270 top
RC9  80.6_0402_1%  [R_0402]  100.89 82.22 270 top
RC10  100_0402_1%  [R_0402]  100.01 82.22 270 top
RC11  0_0402_5%  [R0402_SHORT]  119.06 74.46 180 top
RC12  20K_0402_5%  [R_0402]  117.15 74.59 270 top
RC13  10M_0402_5%  [R_0402]  115.42 88.91 270 top
RC14  20K_0402_5%  [R_0402]  116.26 74.59 270 top
RC16  1M_0402_5%  [R_0402]  115.37 74.59 270 top
RC19  220_0402_1%  [R_0402]  70.01 109.21 90 top
RC20  56_0402_1%  [R_0402]  70.57 111.62 90 top
RC21  0_0402_5%  [R0402_SHORT]  99.04 71.16 0 top
RC24  22_0402_5%  [R_0402]  108.64 69.59 270 top
RC26  100K_0402_5%  [R_0402]  50.98 108.07 0 top
RC27  10K_0402_5%  [R_0402]  105.07 72.18 0 top
RC29  10K_0402_5%  [R_0402]  86.23 119.5 270 bottom
RC30  1M_0402_5%  [R_0402]  90.56 117.32 180 bottom
RC31  51_0201_5%  [R_0201]  76.35 115.99 0 top
RC32  10K_0402_5%  [R_0402]  85.6 117.13 180 bottom
RC34  51_0201_5%  [R_0201]  76.35 116.63 0 top
RC40  0_0402_5%  [R0402_SHORT]  112.13 110.99 270 bottom
RC41  0_0402_5%  [R0402_SHORT]  104.21 70.27 180 top
RC47  0_0402_5%  [R_0402]  106.86 69.59 270 top
RC48  33_0402_5%  [R_0402]  47.73 108.14 180 top
RC52  8.2K_0402_5%  [R_0402]  109.53 69.59 270 top
RC53  1K_0402_1%  [R_0402]  71.23 110.25 270 bottom
RC54  0_0402_5%  [R_0402]  70.34 110.25 270 bottom
RC55  49.9_0402_1%  [R_0402]  111.89 72.05 180 top
RC56  49.9_0402_1%  [R_0402]  53.02 102.02 270 top
RC67  10K_0402_5%  [R_0402]  119.87 94.5 90 bottom
RC70  10K_0402_5%  [R_0402]  120.76 94.25 90 bottom
RC71  10K_0402_5%  [R_0402]  118.95 95.42 270 bottom
RC74  10K_0402_5%  [R_0402]  120.96 91.91 90 bottom
RC83  1K_0402_5%  [R_0402]  116.19 94.81 180 bottom
RC86  10K_0402_5%  [R_0402]  114.13 98.69 90 bottom
RC88  10K_0402_5%  [R_0402]  113.24 98.69 90 bottom
RC92  499_0402_1%  [R_0402]  115.42 97.32 0 top
RC93  499_0402_1%  [R_0402]  115.27 93.82 0 bottom
RC95  8.2K_0402_5%  [R_0402]  120.63 75.83 0 top
RC97  20K_0402_5%  [R_0402]  120.17 72.07 180 top
RC98  1K_0402_5%  [R_0402]  120.17 71.16 180 top
RC99  1K_0402_5%  [R_0402]  121.16 71.41 90 top
RC100  20K_0402_5%  [R_0402]  121.16 73.14 90 top
RC101  1K_0402_5%  [R_0402]  123.88 72.23 90 top
RC102  33_0402_5%  [R_0402]  172.01 55.53 90 top
RC103  33_0402_5%  [R_0402]  138.16 122.49 0 bottom
RC104  1K_0402_5%  [R_0402]  67.82 109.82 90 top
RC105  1K_0402_5%  [R_0402]  67.75 110.53 180 bottom
RC106  4.7K_0402_5%  [R_0402]  79.3 129.88 90 bottom
RC107  4.7K_0402_5%  [R_0402]  76.54 129.22 180 bottom
RC108  10K_0402_5%  [R_0402]  173.46 133.14 0 top
RC109  0_0402_5%  [R0402_SHORT]  114.08 72.58 270 top
RC117  1K_0402_5%  [R_0402]  119.97 111.29 270 bottom
RC118  1K_0402_5%  [R_0402]  120.38 117.2 0 bottom
RC120  100_0402_1%  [R_0402]  96.25 117.64 0 top
RC121  0_0402_5%  [R0402_SHORT]  97.53 115.09 90 top
RC123  10K_0402_5%  [R_0402]  68.26 112.26 0 bottom
RC124  0_0402_5%  [R0402_SHORT]  60.2 110.99 270 top
RC125  100_0402_1%  [R_0402]  61.17 112 180 top
RC126  0_0402_5%  [R0402_SHORT]  100.72 115.25 90 top
RC127  0_0402_5%  [R_0402]  115.37 75.48 90 top
RC132  0_0402_5%  [R0402_SHORT]  116.26 75.48 90 top
RC142  0_0402_5%  [R0402_SHORT]  98.42 115.09 90 top
RC143  100_0402_1%  [R_0402]  98.04 117.63 90 top
RC144  1K_0402_1%  [R_0402]  66.02 110.15 0 top
RC151  49.9_0402_1%  [R_0402]  111.89 71.16 180 top
RC152  49.9_0402_1%  [R_0402]  73.08 110.58 90 top
RC159  100K_0402_5%  [R_0402]  119.44 99.1 270 top
RC165  10K_0402_5%  [R_0402]  124.44 78.09 270 top
RC166  10K_0402_5%  [R_0402]  123.5 78.09 270 top
RC173  0_0603_5%  [R0603_SHORT]  126.82 87.72 180 top
RC176  0_0805_5%  [R0805_SHORT]  139.56 87.81 90 top
RC183  0_0402_5%  [R0402_SHORT]  59.32 110.99 270 top
RC184  100_0402_1%  [R_0402]  59.34 112 180 top
RC185  0_0402_5%  [R0402_SHORT]  99.8 115.25 90 top
RC189  100_0402_1%  [R_0402]  96.96 82.51 90 top
RC192  100_0402_1%  [R_0402]  95.38 89.02 180 top
RC197  0_0603_5%  [R0603_SHORT]  97.59 106.53 180 top
RC200  49.9_0402_1%  [R_0402]  54.11 101.08 90 top
RC201  1K_0402_1%  [R_0402]  66.83 111.39 0 bottom
RC204  100K_0402_5%  [R_0402]  121.24 99.99 180 top
RC209  100K_0402_5%  [R_0402]  121.23 98.85 180 top
RC277  2.2K_0402_5%  [R_0402]  52.91 104.33 0 top
RC286  0_0402_5%  [R_0402]  104.21 71.29 180 top
RC287  2.2K_0402_5%  [R_0402]  52.91 103.44 0 top
RC288  100K_0402_5%  [R_0402]  117.99 99.99 0 top
RC293  0_0603_5%  [R0603_SHORT]  95.81 83.03 90 top
RC294  1K_0402_5%  [R_0402]  71.95 115.36 180 top
RC295  0_0402_5%  [R0402_SHORT]  59.24 75.48 90 top
RC296  0_0402_5%  [R0402_SHORT]  107.83 83 180 top
RC297  1K_0402_5%  [R_0402]  103.23 68.49 0 top
RC298  8.2K_0402_5%  [R_0402]  113.48 113.26 180 bottom
RC299  1K_0402_5%  [R_0402]  99.96 72.05 180 top
RC300  20K_0402_5%  [R_0402]  121.52 74.92 180 top
RC301  20K_0402_5%  [R_0402]  103.23 67.6 0 top
RC302  20K_0402_5%  [R_0402]  99.24 70.17 270 top
RC304  0_0805_5%  [R0805_SHORT]  122.29 89.1 90 top
RC306  1K_0402_5%  [R_0402]  115.42 98.72 0 top
RC307  20K_0402_5%  [R_0402]  117.38 97.98 270 top
RC308  8.2K_0402_5%  [R_0402]  115.36 77.26 0 top
RC310  0_0402_5%  [R0402_SHORT]  109.66 121.25 270 top
RC311  0_0402_5%  [R0402_SHORT]  138.94 117.77 180 bottom
RC312  0_0402_5%  [R0402_SHORT]  126.9 122.98 90 bottom
RC313  0_0402_5%  [R0402_SHORT]  139.07 121.55 180 bottom
RC314  0_0402_5%  [R0402_SHORT]  125.89 122.98 90 bottom
RC315  0_0402_5%  [R0402_SHORT]  123.63 34.44 90 top
RC316  0_0402_5%  [R0402_SHORT]  121.34 33.36 90 top
RC317  0_0402_5%  [R0402_SHORT]  121.6 46.7 90 top
RC326  0_0402_5%  [R0402_SHORT]  116.54 95.57 180 top
RC330  0_0402_5%  [R0402_SHORT]  97.26 71.16 0 top
RC333  0_0402_5%  [R0402_SHORT]  116.27 78.14 180 top
RC341  0_0805_5%  [R0805_SHORT]  126.89 70.84 180 top
RC344  24.9_0402_1%  [R_0402]  81.03 104.76 270 top
RC348  33_0402_5%  [R_0402]  47.73 109.03 180 top
RC350  20K_0402_5%  [R_0402]  117.91 94.76 180 bottom
RC351  10K_0402_5%  [R_0402]  112.99 65.17 90 top
RC352  51_0201_5%  [R_0201]  78.99 116.02 90 bottom
RC353  51_0201_5%  [R_0201]  74.99 115.38 90 top
RC354  51_0201_5%  [R_0201]  76.93 118.47 180 top
RC355  0_0402_5%  [R_0402]  104.75 90.48 180 top
RC356  1K_0402_5%  [R_0402]  103.31 63.73 0 top
RC372  10K_0402_5%  [R_0402]  128.96 87.54 180 top
RC373  0_0402_5%  [R0402_SHORT]  104.21 72.18 180 top
RC374  100_0402_1%  [R_0402]  99.8 117.51 90 top
RC375  100_0402_1%  [R_0402]  101.63 115.25 90 top
RC376  10K_0402_5%  [R_0402]  122.99 72.23 90 top
RC378  200_0402_1%  [R_0402]  113.9 93.11 270 bottom
RC379  2.7K_0402_1%  [R_0402]  94.49 106.67 90 top
RC380  0_0402_5%  [R0402_SHORT]  127.54 90.51 180 bottom
RC381  5P_0402_50V8-C  [C_0402]  112.58 109.39 90 top
RC382  5P_0402_50V8-C  [C_0402]  105.59 69.59 270 top
RC383  5P_0402_50V8-C  [C_0402]  105.91 70.39 90 top
RC384  113_0402_1%  [R_0402]  112.88 93.11 270 bottom
RC385  100_0402_1%  [R_0402]  116.41 109.26 0 top
RC386  5P_0402_50V8-C  [C_0402]  115.4 99.33 270 bottom
RC387  100_0402_1%  [R_0402]  69.22 111.62 90 top
RC388  100_0402_1%  [R_0402]  71.84 110.12 270 top
RC389  200_0402_1%  [R_0402]  119.68 89.7 0 top
RC390  1.5K_0402_5%  [R_0402]  111.44 115.34 90 top
RC391  100K_0402_1%  [R_0402]  70.9 110.12 270 top
RC392  10K_0402_5%  [R_0402]  109.45 63.02 90 top
RC393  10K_0402_5%  [R_0402]  117.02 62.19 90 top
RC394  1K_0402_5%  [R_0402]  121.29 118.09 180 bottom
RC395  10K_0402_5%  [R_0402]  128.05 82.95 180 top
RC396  10K_0402_5%  [R_0402]  128.05 83.83 180 top
RC397  2.2K_0402_1%  [R_0402]  128.05 84.72 180 top
RC398  2.2K_0402_1%  [R_0402]  128.05 85.61 180 top
RC399  10K_0402_5%  [R_0402]  118.04 62.19 90 top
RC400  10K_0402_5%  [R_0402]  78.97 130.09 0 top
RC401  1K_0402_5%  [R_0402]  79.64 127.1 180 top
RC402  0_0402_5%  [R_0402]  165.66 177.15 270 top
RC403  10K_0402_5%  [R_0402]  104.21 69.38 180 top
RC406  1K_0402_5%  [R_0402]  105.96 90.46 0 top
RC407  1K_0402_5%  [R_0402]  107.04 89.57 0 top
RC409  10K_0402_5%  [R_0402]  223.77 62.16 270 bottom
RC410  60.4_0402_1%  [R_0402]  68.81 113.9 0 bottom
RC411  0_0402_5%  [R0402_SHORT]  119.18 94.53 180 top
RC413  10K_0402_5%  [R_0402]  33.78 104.55 90 top
RC415  0_0201_5%  [R_0201]  73.34 112.65 90 bottom
RC422  0_0201_5%  [R_0201]  76.35 115.36 0 top
RC423  0_0201_5%  [R_0201]  79.69 113.68 270 bottom
RC424  0_0201_5%  [R_0201]  75.62 115.97 270 top
RC425  0_0201_5%  [R_0201]  75.85 113.39 180 bottom
RC426  51_0201_5%  [R_0201]  73.31 115.42 180 top
RC427  0_0402_5%  [R_0402]  146.54 96.62 0 top
RC428  0_0402_5%  [R_0402]  118.28 95.42 0 top
RC429  0_0402_5%  [R_0402]  145.55 95.23 180 top
RC430  0_0402_5%  [R_0402]  175.13 50.7 90 top
RC431  0_0402_5%  [R_0402]  176.08 51.61 270 top
RC432  0_0402_5%  [R_0402]  176.97 51.61 270 top
RC433  10K_0402_5%  [R_0402]  125.99 69.45 180 top
RC434  10K_0402_5%  [R_0402]  118.29 97.97 270 top
